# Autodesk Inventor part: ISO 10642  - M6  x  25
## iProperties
IsCustomPart: 0
Created: 2007-03
Part Number: ISO 10642  - M6  x  25
Material: Stahl
Description: Innensechskantschraube mit Senkkopf
Document SubType Name: Modeling
Standard: ISO 10642
Designer: Goedde
Standards Organization: DIN
Language: de-DE
Size Designation: M6  x  25
Categories: <MemberInstance><Categories><Category DisplayName="Schrauben" InternalName="e4da775c-781d-43d5-af7c-5136215cf5a6" Mnemonic="FSTN"><Category DisplayName="Bolzen"
Mass: 6.51007 g
Surface Area: 6.97638 cm^2
Volume: 0.829308 cm^3
Density: 7.85 g/cm^3
Author: Goedde
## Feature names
1. Körper [Revolution]
2. Loch [Extrusion]
3. Fase1 [Chamfer]
